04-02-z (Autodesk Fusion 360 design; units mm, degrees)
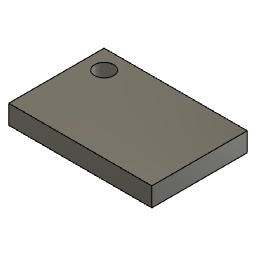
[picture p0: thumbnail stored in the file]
sketch "スケッチ" plane through (0, 0, 0) normal (0, 1, 0) x axis (1, 0, 0)
  line L1 (-15, 10) -> (15, 10)
  line L2 (-15, -10) -> (-15, 10)
  line L3 (15, -10) -> (-15, -10)
  line L4 (15, 10) -> (15, -10)
  line L5 (-15, -10) -> (15, 10)
  line L6 (15, -10) -> (-15, 10)
  point P6 (0, 0)
  point P1 (0, 0)
  point P2 (15, 10)
  point P3 (-15, 10)
  point P5 (15, -10)
  horizontal L1
  perpendicular L1 L2
  parallel L1 L3
  parallel L2 L4
  coincident L5 P6
  coincident L6 P6
  coincident P1 P6
  dimension "d5" distance P2 P3 = 30
  dimension "d6" distance P2 P5 = 20
extrude "押し出し" new body sketch "スケッチ" profile of L1 L2 L3 L4 along normal blind 4
hole "穴" HoleDepth 4 HoleDiameter 4 TipAngle 118 RefDim1 4 RefDim2 4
